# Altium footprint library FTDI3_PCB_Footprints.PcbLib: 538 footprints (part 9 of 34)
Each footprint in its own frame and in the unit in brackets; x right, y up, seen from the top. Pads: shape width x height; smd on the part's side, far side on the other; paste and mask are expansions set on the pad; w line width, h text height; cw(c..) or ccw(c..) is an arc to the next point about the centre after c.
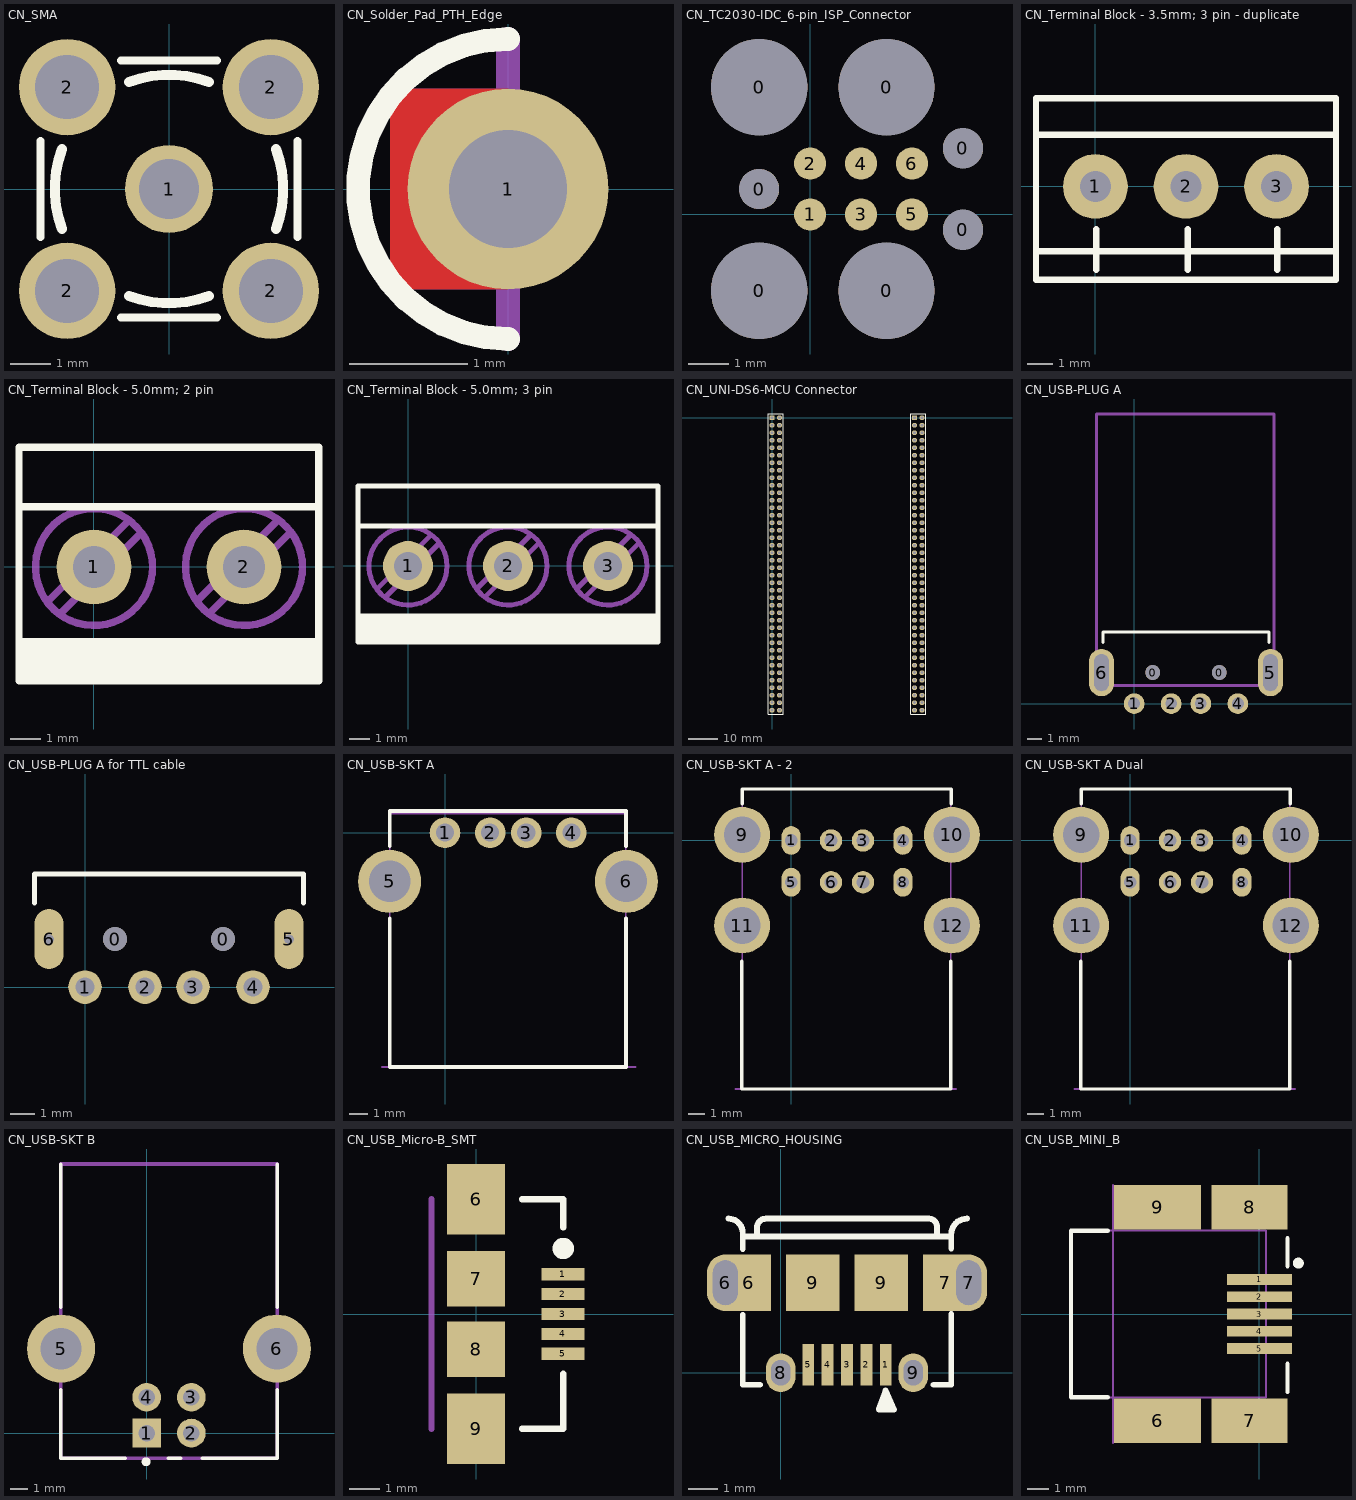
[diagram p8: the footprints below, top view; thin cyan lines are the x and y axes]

## CN_SMA [mm] "SMA Straight PCB Socket"
pads (5):
  round 2.2 hole 1.5: 1(0,0)
  round 2.4 hole 1.6: 2(-2.54,-2.54) 2(-2.54,2.54) 2(2.54,-2.54) 2(2.54,2.54)
Top Overlay:
  lines w0.2: -3.2,-1.2 -3.2,1.2 ; -1.2,-3.2 1.2,-3.2 ; -1.2,3.2 1.2,3.2 ; 3.2,-1.2 3.2,1.2
  lines w0.254: -2.67,-0.998 cw(c0,0) -2.67,0.998 ; -0.998,-2.67 ccw(c0,0) 0.998,-2.67 ; -0.998,2.67 cw(c0,0) 0.998,2.67 ; 2.67,-0.998 ccw(c0,0) 2.67,0.998

## CN_Solder_Pad_PTH_Edge [mm] "Soldering pad for PCB on PCB designs"
height 4.6
pads (1):
  round 1.7 hole 1: 1(0,0)
Top Layer:
  rectangle: -1,-0.85 0,0.85
Bottom Layer:
  rectangle: -1,-0.85 0,0.85
Top Overlay:
  lines w0.2: 0,-1.27 cw(c0,0) 0,1.27
Mechanical 1:
  lines w0.2: 0,-1.27 0,1.27

## CN_TC2030-IDC_6-pin_ISP_Connector [mm] "TC2030-IDC-10 6-Pin Tag-Connect Plug-of-Nails(tm) Legged Spring-Pin Cable with Ribbon; Tag-Connect"
pads (13):
  round 2.4 hole 2.4 unplated: 0(-1.27,-1.905) 0(-1.27,3.175) 0(1.905,-1.905) 0(1.905,3.175)
  round 1 hole 1 unplated: 0(-1.27,0.635) 0(3.81,-0.381) 0(3.81,1.651)
  round 0.8 smd paste-1: 1(0,0) 2(0,1.27) 3(1.27,0) 4(1.27,1.27) 5(2.54,0) 6(2.54,1.27)

## CN_Terminal Block - 3.5mm; 3 pin - duplicate [mm] "3pin; Terminal Block Connector; 5.0mm pitch; Phoenix Contact; 1729021"
height 10
pads (3):
  round 2.5 hole 1.2: 1(0,0) 2(3.5,0) 3(7,0)
Top Overlay:
  lines w0.25: -2.3,-2.5 9.3,-2.5 ; -2.3,2 9.3,2 ; 0.025,-3.225 0.025,-1.65 ; 3.575,-3.225 3.575,-1.65 ; 7.025,-3.225 7.025,-1.65 ; -2.3,-3.6 9.3,-3.6 9.3,3.4 -2.3,3.4 -2.3,-3.6
3D body: height 9, standoff 0, extent -2.375,-3.675 9.475,3.4

## CN_Terminal Block - 5.0mm; 2 pin [mm] "2pin; Terminal Block Connector; 5.0mm pitch; Phoenix Contact; 1729018"
height 10
pads (2):
  round 2.5 hole 1.4: 1(0,0) 2(5,0)
Top Overlay:
  rectangle: -2.5,-3.8 7.5,-2.55
  lines w0.25: -2.5,-2.5 7.5,-2.5 ; -2.5,2 7.5,2 ; -2.5,-3.8 -2.5,4 7.5,4 7.5,-3.8 -2.5,-3.8
M13_Assembly_Info:
  circle w0.25: c5,0 r1.95
  circle w0.25: c0,0 r1.95
  lines w0.25: -1.556,-1.167 1.167,1.556 ; -1.149,-1.573 1.573,1.149 ; 3.427,-1.149 6.149,1.573 ; 3.833,-1.556 6.556,1.167
3D body: height 9, standoff 0, extent -2.375,-3.675 7.375,3.875

## CN_Terminal Block - 5.0mm; 3 pin [mm] "3pin; Terminal Block Connector; 5.0mm pitch; Phoenix Contact; 1729021"
height 10
pads (3):
  round 2.5 hole 1.4: 1(0,0) 2(5,0) 3(10,0)
Top Overlay:
  rectangle: -2.5,-3.8 12.5,-2.525
  lines w0.25: -2.5,-2.5 12.5,-2.5 ; -2.5,2 12.5,2 ; -2.5,-3.8 -2.5,4 12.5,4 12.5,-3.8 -2.5,-3.8
M13_Assembly_Info:
  circle w0.25: c5,0 r1.95
  circle w0.25: c0,0 r1.95
  circle w0.25: c10,0 r1.95
  lines w0.25: -1.556,-1.167 1.167,1.556 ; -1.149,-1.573 1.573,1.149 ; 3.427,-1.149 6.149,1.573 ; 3.833,-1.556 6.556,1.167 ; 8.427,-1.149 11.149,1.573 ; 8.833,-1.556 11.556,1.167
3D body: height 9, standoff 0, extent -2.375,-3.675 12.375,3.875

## CN_UNI-DS6-MCU Connector [mil] "MCU Connector for UNI-DS6 Board from Mikroelektronika"
height 329.92
pads (160):
  rect 65x65 hole 39.37: 1(0,0) 81(1900,0)
  round 65 hole 39.37: 2(100,0) 3(0,-100) 4(100,-100) 5(0,-200) 6(100,-200) 7(0,-300) 8(100,-300) 9(0,-400) 10(100,-400) 11(0,-500) 12(100,-500) 13(0,-600) 14(100,-600) 15(0,-700) 16(100,-700) 17(0,-800) 18(100,-800) 19(0,-900) 20(100,-900) 21(0,-1000) 22(100,-1000) 23(0,-1100) 24(100,-1100) 25(0,-1200) 26(100,-1200) 27(0,-1300) 28(100,-1300) 29(0,-1400) 30(100,-1400) 31(0,-1500) 32(100,-1500) 33(0,-1600) 34(100,-1600) 35(0,-1700) 36(100,-1700) 37(0,-1800) 38(100,-1800) 39(0,-1900) 40(100,-1900) 41(0,-2000) 42(100,-2000) 43(0,-2100) 44(100,-2100) 45(0,-2200) 46(100,-2200) 47(0,-2300) 48(100,-2300) 49(0,-2400) 50(100,-2400) 51(0,-2500) 52(100,-2500) 53(0,-2600) 54(100,-2600) 55(0,-2700) 56(100,-2700) 57(0,-2800) 58(100,-2800) 59(0,-2900) 60(100,-2900) 61(0,-3000) 62(100,-3000) 63(0,-3100) 64(100,-3100) 65(0,-3200) 66(100,-3200) 67(0,-3300) 68(100,-3300) 69(0,-3400) 70(100,-3400) 71(0,-3500) 72(100,-3500) 73(0,-3600) 74(100,-3600) 75(0,-3700) 76(100,-3700) 77(0,-3800) 78(100,-3800) 79(0,-3900) 80(100,-3900) 82(2000,0) 83(1900,-100) 84(2000,-100) 85(1900,-200) 86(2000,-200) 87(1900,-300) 88(2000,-300) 89(1900,-400) 90(2000,-400) 91(1900,-500) 92(2000,-500) 93(1900,-600) 94(2000,-600) 95(1900,-700) 96(2000,-700) 97(1900,-800) 98(2000,-800) 99(1900,-900) 100(2000,-900) 101(1900,-1000) 102(2000,-1000) 103(1900,-1100) 104(2000,-1100) 105(1900,-1200) 106(2000,-1200) 107(1900,-1300) 108(2000,-1300) 109(1900,-1400) 110(2000,-1400) 111(1900,-1500) 112(2000,-1500) 113(1900,-1600) 114(2000,-1600) 115(1900,-1700) 116(2000,-1700) 117(1900,-1800) 118(2000,-1800) 119(1900,-1900) 120(2000,-1900) 121(1900,-2000) 122(2000,-2000) 123(1900,-2100) 124(2000,-2100) 125(1900,-2200) 126(2000,-2200) 127(1900,-2300) 128(2000,-2300) 129(1900,-2400) 130(2000,-2400) 131(1900,-2500) 132(2000,-2500) 133(1900,-2600) 134(2000,-2600) 135(1900,-2700) 136(2000,-2700) 137(1900,-2800) 138(2000,-2800) 139(1900,-2900) 140(2000,-2900) 141(1900,-3000) 142(2000,-3000) 143(1900,-3100) 144(2000,-3100) 145(1900,-3200) 146(2000,-3200) 147(1900,-3300) 148(2000,-3300) 149(1900,-3400) 150(2000,-3400) 151(1900,-3500) 152(2000,-3500) 153(1900,-3600) 154(2000,-3600) 155(1900,-3700) 156(2000,-3700) 157(1900,-3800) 158(2000,-3800) 159(1900,-3900) 160(2000,-3900)
Top Overlay:
  lines w7.87: -50,-3950.39 150,-3950.39 150,-1750 150,50 -50,50 -50,-1750 -50,-3950.39 ; 1850,-3950.39 1850,-1750 1850,50 2050,50 2050,-1750 2050,-3950.39 1850,-3950.39

## CN_USB-PLUG A [mm] "Connector; USB2.0, Type A, Thru-Hole; 4 Position; Right Angle"
pads (8):
  round 1 hole 1 unplated: 0(1.25,2.1) 0(5.75,2.1)
  round 1.4 hole 0.8: 1(0,0) 2(2.5,0) 3(4.5,0) 4(7,0)
  oval 1.7x3.2 hole 1 slot 2.5 at 90 deg: 5(9.2,2.1) 6(-2.2,2.1)
Top Overlay:
  lines w0.2: -2.1,4.115 -2.1,4.825 ; -2.1,4.835 9.1,4.835 ; 9.1,4.115 9.1,4.825
M13_Assembly_Info:
  lines w0.2: -2.55,19.555 -2.55,1.225 9.45,1.225 9.45,19.555 ; -2.55,19.555 -2.55,19.555 ; -2.55,19.555 9.45,19.555 ; 9.45,19.555 9.45,19.555
3D body: height 1.88, standoff -2.62, extent -2.55,1.225 9.45,19.555

## CN_USB-PLUG A for TTL cable [mm] "Connector; USB2.0, Type A, Thru-Hole; 4 Position; Right Angle"
pads (8):
  round 1 hole 1 unplated: 0(1.25,2) 0(5.75,2)
  round 1.4 hole 0.8: 1(0,0) 2(2.5,0) 3(4.5,0) 4(7,0)
  oval 1.2x2.5 hole 0.4: 5(8.5,2) 6(-1.5,2)
Top Overlay:
  lines w0.2: -2.1,3.5 -2.1,4.71 9.1,4.71 9.1,3.5

## CN_USB-SKT A [mm] "Connector; USB2.0, Type A, Thru-Hole; 4 Position; Right Angle"
pads (6):
  round 1.7 hole 1: 1(-0.01,0) 2(2.49,0) 3(4.49,0) 4(6.99,0)
  round 3.5 hole 2.3: 5(-3.08,-2.7) 6(10.04,-2.7)
Top Overlay:
  lines w0.2: -3.08,-4.75 -3.08,-12.98 10.02,-12.98 10.02,-4.75 ; -3.08,-0.75 -3.08,1.2 10.02,1.2 10.02,-0.75
M13_Assembly_Info:
  lines w0.1: -3.5,-12.975 10.55,-12.975 ; -3.075,1.025 -3.075,-12.95 -3.05,-12.975 10,-12.975 10,1.05 -3.05,1.05
3D body: height 7.57, standoff -3.28, extent -4.425,-13.035 11.375,1.125

## CN_USB-SKT A - 2 [mm] "Connector; USB2.0, Type A, Thru-Hole; 4 Position; Right Angle"
pads (12):
  oval 1.2x1.8 hole 0.8: 1(0,0) 4(7,0) 5(0,-2.62) 8(7,-2.62)
  round 1.4 hole 0.8: 2(2.5,0) 3(4.5,0) 6(2.5,-2.62) 7(4.5,-2.62)
  round 3.5 hole 2.3: 9(-3.07,0.35) 10(10.07,0.35) 11(-3.07,-5.33) 12(10.07,-5.33)
Top Overlay:
  lines w0.2: -3.095,-7.55 -3.095,-15.575 10.005,-15.575 10.005,-7.55 ; -3.07,2.3 -3.07,3.225 10.03,3.225 10.03,2.3
M13_Assembly_Info:
  lines w0.1: -3.5,-15.575 10.35,-15.575 ; -3.065,-15.575 -3.065,3.225 10.01,3.225 10.01,-15.575 -3.065,-15.575
3D body: height 16.17, standoff -3.97, extent -4.659,-15.58 11.58,1.6

## CN_USB-SKT A Dual [mm] "Connector; USB2.0, Type A, Thru-Hole; 4 Position; Right Angle"
pads (12):
  oval 1.2x1.8 hole 0.8: 1(0,0) 4(7,0) 5(0,-2.62) 8(7,-2.62)
  round 1.4 hole 0.8: 2(2.5,0) 3(4.5,0) 6(2.5,-2.62) 7(4.5,-2.62)
  round 3.5 hole 2.3: 9(-3.07,0.35) 10(10.07,0.35) 11(-3.07,-5.33) 12(10.07,-5.33)
Top Overlay:
  lines w0.2: -3.095,-7.55 -3.095,-15.575 10.005,-15.575 10.005,-7.55 ; -3.07,2.3 -3.07,3.225 10.03,3.225 10.03,2.3
M13_Assembly_Info:
  lines w0.1: -3.5,-15.575 10.35,-15.575 ; -3.065,-15.575 -3.065,3.225 10.01,3.225 10.01,-15.575 -3.065,-15.575
3D body: height 0, standoff 0, extent -3.075,-15.6 10,3.175

## CN_USB-SKT B [mm] "Connector; USB2.0, Type B, Thru-Hole; 4 Position; Right Angle"
height 10.95
pads (6):
  rect 1.6x1.6 hole 0.92: 1(0,0)
  round 1.6 hole 0.92: 2(2.5,0) 3(2.5,2) 4(0,2)
  round 3.8 hole 2.3: 5(-4.77,4.71) 6(7.27,4.71)
Top Overlay:
  circle w0.25: c-0.025,-1.6 r0.125
  lines w0.2: -4.8,2.41 -4.8,-1.4 -1.2,-1.4 ; -4.8,7.01 -4.8,14.99 ; 1.2,-1.4 1.9,-1.4 ; 3.1,-1.4 7.3,-1.4 7.3,2.41 ; 7.3,7.01 7.3,14.99
M13_Assembly_Info:
  lines w0.2: -4.8,-1.4 7.3,-1.4 7.3,15.01 -4.8,15.01 -4.8,-1.4
3D body: height 11.02, standoff -3.7, extent -6.199,-1.3 8.699,15

## CN_USB_Micro-B_SMT [mm] "USB-Micro-B connector SMT"
pads (9):
  rect 1.4x0.4 smd: 1(2.84,1.3) 2(2.84,0.65) 3(2.84,0) 4(2.84,-0.65) 5(2.84,-1.3)
  rect 1.9x2.3 smd: 6(0,3.75) 9(0,-3.75)
  rect 1.9x1.8 smd: 7(0,1.15) 8(0,-1.15)
Top Overlay:
  circle w0.5: c2.85,2.14 r0.1
  lines w0.2: 1.5,-3.75 2.85,-3.75 2.85,-1.95 ; 1.5,3.75 2.85,3.75 2.85,2.82
Mechanical 1:
  lines w0.2: -1.45,-3.75 -1.45,3.75
3D body: height 2.77, standoff -0.18, extent -2.76,-4.037 2.84,4.037

## CN_USB_MICRO_HOUSING [mm] "Micro_USB2.0_SMT_Housing Holes"
height 2.2
pads (13):
  rect 0.4x1.4 smd: 1(3.525,0.27) 2(2.875,0.27) 3(2.225,0.27) 4(1.575,0.27) 5(0.925,0.27)
  oval 1.23x1.9 hole 0.83 slot 1.5 at 90 deg: 6(-1.86,3.02) 7(6.31,3.02)
  rect 1.5x1.9 smd: 6(-1.075,3.02) 7(5.525,3.02)
  oval 1x1.3 hole 0.65 slot 0.85 at 90 deg: 8(0,0) 9(4.45,0)
  rect 1.8x1.9 smd: 9(1.075,3.02) 9(3.375,3.02)
Top Overlay:
  lines w0.2: -1.75,5.17 cw(c-1.75,4.695) -1.275,4.695 -1.275,4.57 ; -1.275,1.945 -1.275,-0.405 -0.7,-0.405 ; -1.275,4.145 -1.275,4.57 ; -0.8,4.57 -0.8,4.87 cw(c-0.5,4.87) -0.5,5.17 4.975,5.17 cw(c4.975,4.895) 5.25,4.895 5.25,4.62 ; 3.425,-1.03 3.575,-1.155 3.525,-0.605 ; 5.125,-0.405 5.725,-0.405 5.725,1.97 ; 5.725,4.17 5.725,4.57 ; 6.25,5.17 ccw(c6.25,4.645) 5.725,4.645 5.725,4.57 ; -1.275,4.57 5.725,4.57 ; 3.525,-0.605 3.8,-1.23 3.3,-1.23 3.525,-0.605
3D body: height 2.77, standoff -0.18, extent -1.812,-0.38 6.262,5.22

## CN_USB_MINI_B [mm] "USB Mini-B Connector"
height 5
pads (9):
  rect 3x0.5 smd: 1(0,1.6) 2(0,0.8) 3(0,0) 4(0,-0.8) 5(0,-1.6)
  rect 4x2.05 smd: 6(-4.7,-4.925) 9(-4.7,4.925)
  rect 3.5x2.05 smd: 7(-0.45,-4.925) 8(-0.45,4.925)
Top Overlay:
  circle w0.25: c1.8,2.35 r0.125
  lines w0.2: -7,-3.85 -8.7,-3.85 -8.7,3.85 -7,3.85 ; 1.3,-3.6 1.3,-2.3 ; 1.3,2.2 1.3,3.5
Mechanical 1:
  lines w0.1: -6.75,-5.95 -6.75,5.95
M13_Assembly_Info:
  lines w0.1: -8.7,-3.85 -8.7,3.85 0.3,3.85 0.3,-3.85 -8.7,-3.85
3D body: height 3.97, standoff -0.98, extent -8.35,-5.35 0.85,5.35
